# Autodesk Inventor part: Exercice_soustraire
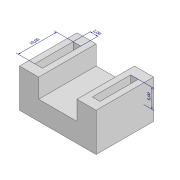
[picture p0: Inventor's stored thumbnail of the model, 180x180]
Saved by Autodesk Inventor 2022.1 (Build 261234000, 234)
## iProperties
Created: 2021-05
Part Number: Exercice_soustraire
Material: Générique
Document SubType Name: Modeling
Designer: Fabian
Density: 1 g/cm^3
Appearance: Par défaut
Mass: 2.05 g
Surface Area: 15.9 cm^2
Volume: 2.05 cm^3
Author: Fabian
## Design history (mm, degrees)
node "Annotations"
  node "Cote linéaire 1" dims "d29" = 10 (derived)
  node "Cote linéaire 2" dims "d32" = 2 (derived)
  node "Cote linéaire 3" dims "d35" = 5 (derived)
sketch "Esquisse1"
  geometry: L1 (0, 0)-(0, 10); L2 (5, 10)-(10, 10); L3 (10, 10)-(10, 0); L4 (10, 0)-(-10, 0); L5 (-10, 0)-(-10, 10); L6 (-10, 10)-(-5, 10); L7 (-5, 10)-(-5, 5); L8 (-5, 5)-(5, 5); L9 (5, 5)-(5, 10)
  constraints: 18 end point, 5 perpendicular, 2 point on line, 2 vertical, 1 horizontal, 1 horizontal alignment, 1 midpoint, 1 other
  dimensions: "d4" = 10 distance of L4.end L5.end; "d5" = 5 distance of L6.end L7.end; "d6" = 20 distance of L3.end L4.end; "d7" = 10 distance of L7.end L8.end
extrude "Extrusion1" new body sketch "Esquisse1" distance "d8" = 10; taper "d10" = 0 deg; dims "d9" = 5, "d11" = 0
sketch "Esquisse6"
  geometry: L1 (1.5, 12.5)-(3.5, 12.5); L2 (3.5, 12.5)-(3.5, 2.5); L3 (3.5, 2.5)-(1.5, 2.5); L4 (1.5, 2.5)-(1.5, 12.5); L5 (0, 15)-(5, 15) reference; L6 (5, 15)-(5, 0) reference; L7 (-5, 15)-(-5, 0); L8 (0, 0)-(-10, 0) reference; L9 (-10, 15)-(0, 15) reference; L10 (-11.5, 12.5)-(-13.5, 12.5); L11 (-13.5, 12.5)-(-13.5, 2.5); L12 (-13.5, 2.5)-(-11.5, 2.5); L13 (-11.5, 2.5)-(-11.5, 12.5); 7 further points
  constraints: 18 end point, 6 midpoint, 6 symmetric about line, 2 parallel, 1 horizontal, 1 horizontal alignment, 1 perpendicular, 1 vertical, 1 vertical alignment
  dimensions: "d17" = 10 distance of L1.end L2.end; "d18" = 2 distance of L1.start L1.end
extrude "Extrusion3" cut sketch "Esquisse6" distance "d19" = 5; taper "d20" = 0 deg
node "Solide1"
other parameters: "d27" = 0 (derived), "d30" = 0 (derived), "d33" = 0 (derived)
